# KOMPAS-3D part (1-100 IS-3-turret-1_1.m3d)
File: created 26.02.2017 18:13:02, last saved 26.02.2017 20:48:16.
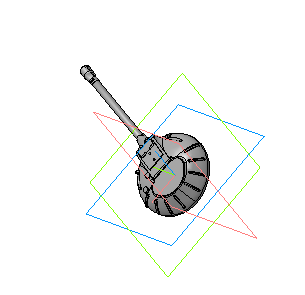
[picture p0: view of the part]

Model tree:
1. Операция без истории:1
2. Масштабирование:1
     Коэффициент = 0.96
3. Эскиз:1
4. Операция выдавливания:1
     Расстояние 1 = 8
